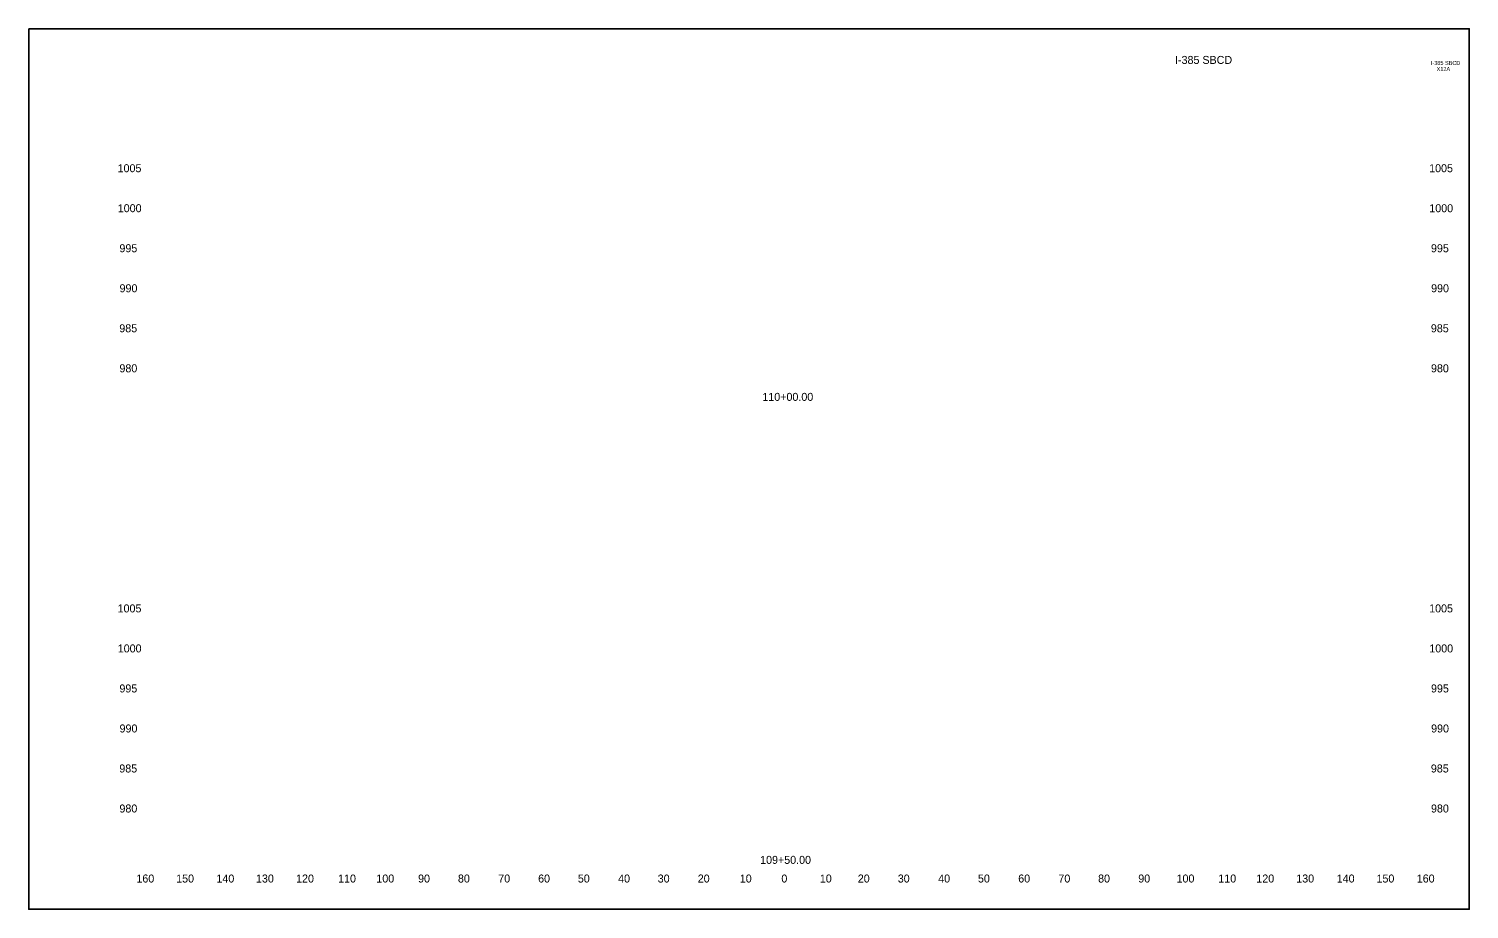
# Model space of a CAD drawing. Extents: x 4994 to 6876, y 4997 to 8804.
# Drawn here: x 6516.2 to 6876.2, y 5390.8 to 5610.8 of the extents above; entities that cross this region are included whole.
import ezdxf

# ---------------------------------------------------------------- set-up
doc = ezdxf.new("R2010")
doc.units = 0
for name, color, linetype in [('RD_SHT_ID', 7, 'Continuous'), ('RD_SHT_IplotShp', 7, 'Continuous'), ('RD_XS_TX_Offset', 7, 'Continuous'), ('RD_XS_TX_Station', 7, 'Continuous')]:
    doc.layers.add(name, color=color, linetype=linetype)

msp = doc.modelspace()

# ---------------------------------------------------------------- linework, layer by layer
at = {"layer": 'RD_SHT_IplotShp'}
msp.add_lwpolyline([(6516.21, 5610.84), (6876.21, 5610.84), (6876.21, 5390.84), (6516.21, 5390.84)], close=True, dxfattribs=at)

# ---------------------------------------------------------------- texts
at = {"layer": 'RD_SHT_ID'}
for s, height, p in [('I-385 SBCD', 2, (6802.69, 5602.06)), ('I-385 SBCD', 1, (6866.63, 5601.8)), ('X12A', 1, (6868.08, 5600.3))]:
    msp.add_text(s, height=height, dxfattribs=at).set_placement(p)
at = {"layer": 'RD_XS_TX_Offset'}
for s, p in [('1005', (6538.4, 5575)), ('1005', (6866.2, 5575)), ('1000', (6538.44, 5565)), ('1000', (6866.24, 5565)), ('995', (6538.86, 5555)), ('995', (6866.66, 5555)), ('990', (6538.89, 5545)), ('990', (6866.69, 5545)), ('985', (6538.83, 5535)), ('985', (6866.63, 5535)), ('980', (6538.86, 5525)), ('980', (6866.66, 5525)), ('1005', (6538.4, 5465)), ('1005', (6866.2, 5465)), ('1000', (6538.44, 5455)), ('1000', (6866.24, 5455)), ('995', (6538.86, 5445)), ('995', (6866.66, 5445)), ('990', (6538.89, 5435)), ('990', (6866.69, 5435)), ('985', (6538.83, 5425)), ('985', (6866.63, 5425)), ('980', (6538.86, 5415)), ('980', (6866.66, 5415)), ('160', (6543.1, 5397.5)), ('150', (6553.04, 5397.5)), ('140', (6563.1, 5397.5)), ('130', (6572.99, 5397.5)), ('120', (6583.01, 5397.5)), ('110', (6593.51, 5397.5)), ('100', (6603.07, 5397.5)), ('90', (6613.5, 5397.5)), ('80', (6623.46, 5397.5)), ('70', (6633.54, 5397.5)), ('60', (6643.5, 5397.5)), ('50', (6653.43, 5397.5)), ('40', (6663.5, 5397.5)), ('30', (6673.39, 5397.5)), ('20', (6683.4, 5397.5)), ('10', (6693.91, 5397.5)), ('0', (6704.3, 5397.5)), ('0', (6704.3, 5397.5)), ('10', (6713.91, 5397.5)), ('20', (6723.4, 5397.5)), ('30', (6733.39, 5397.5)), ('40', (6743.5, 5397.5)), ('50', (6753.43, 5397.5)), ('60', (6763.5, 5397.5)), ('70', (6773.54, 5397.5)), ('80', (6783.46, 5397.5)), ('90', (6793.5, 5397.5)), ('100', (6803.07, 5397.5)), ('110', (6813.51, 5397.5)), ('120', (6823.01, 5397.5)), ('130', (6832.99, 5397.5)), ('140', (6843.1, 5397.5)), ('150', (6853.04, 5397.5)), ('160', (6863.1, 5397.5))]:
    msp.add_text(s, height=2, dxfattribs=at).set_placement(p)
at = {"layer": 'RD_XS_TX_Station'}
for s, p in [('110+00.00', (6699.55, 5517.86)), ('109+50.00', (6698.99, 5402.16))]:
    msp.add_text(s, height=2, dxfattribs=at).set_placement(p)

doc.saveas('drawing.dxf')
